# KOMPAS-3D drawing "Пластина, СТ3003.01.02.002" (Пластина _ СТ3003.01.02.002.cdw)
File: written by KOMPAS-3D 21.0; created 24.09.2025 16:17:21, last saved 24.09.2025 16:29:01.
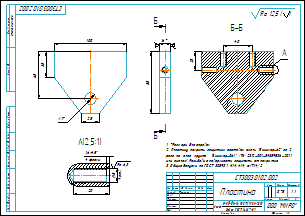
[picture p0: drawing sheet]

Sheet 1: A3, landscape

Document properties: Знак неуказанной шероховатости: 4; Параметр неуказанной шероховатости: Ra 12,5; Масса: 0.780129; Полное имя файла: ..\..\3D\Кронштейн _ СТ3003.01.02.000\Пластина _ СТ3003.01.02.002.m3d

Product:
- Part/product: Пластина  | designation СТ3003.01.02.002
    Материал: Лист$dБ-ПН-НО-16 ГОСТ 19903-2015;Ст3сп ГОСТ 14637-89$ (density 7850 kg/m3)
    Масса: 0.780129

Title block, sheet 1: Наименование: Пластина; designation: СТ3003.01.02.002; Материал: Лист Б-ПН-НО-16 ГОСТ 19903-2015 Ст3сп ГОСТ 14637-89; Масса: 0,78; Количество листов документа: 1; organisation: ООО "МИРО"; Форматы листов документа: A3; stored path: C:\Users\1\Yandex.Disk\Документы\Новая папка\Стапель №2\Стапель _ СТ3003.00.00.000\Опора _ СТ3003.01.00.000\2D\Кронштейн _ СТ3003.01.02.000\Пластина _ СТ3003.01.02.002.cdw; Разработал: Тимонин

Views: Вид 1, Слева, Проекционный вид 2, Разрез А-А, Выносной элемент 4, Разрез Б-Б, Выносной элемент А, Выносной элемент
Referenced files in C:\Users\1\Yandex.Disk\Документы\Новая папка\Стапель №2\Стапель _ СТ3003.00.00.000\Опора _ СТ3003.01.00.000\3D\Кронштейн _ СТ3003.01.02.000\: Пластина _ СТ3003.01.02.002.m3d
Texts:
  Ra 6,3
  Ra 12,5
  Ra 12,5 ( )
  СТ3003.01.02.000
  СТ3003.01.02.002 Пластина
Dimensions and other numbers on the sheet: 100; 35; 65; 17; 25; 85; 16; 40; 20; 1,6; 4 фаски; 8; 4 отв.; 1:1; 1; 0,78

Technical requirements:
  *Размеры для справок.
  Пластину покрыть защитным составом эмаль "Виникор-62" за 2
  раза по слою грунта  "Виникор-061" (ТУ 2312-001-54359536-2011
  или аналог). Резьбовые поверхности защитить от покрытия.
  Общие допуски по ГОСТ 30893.1: Н14, h14, ± IT14/2.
